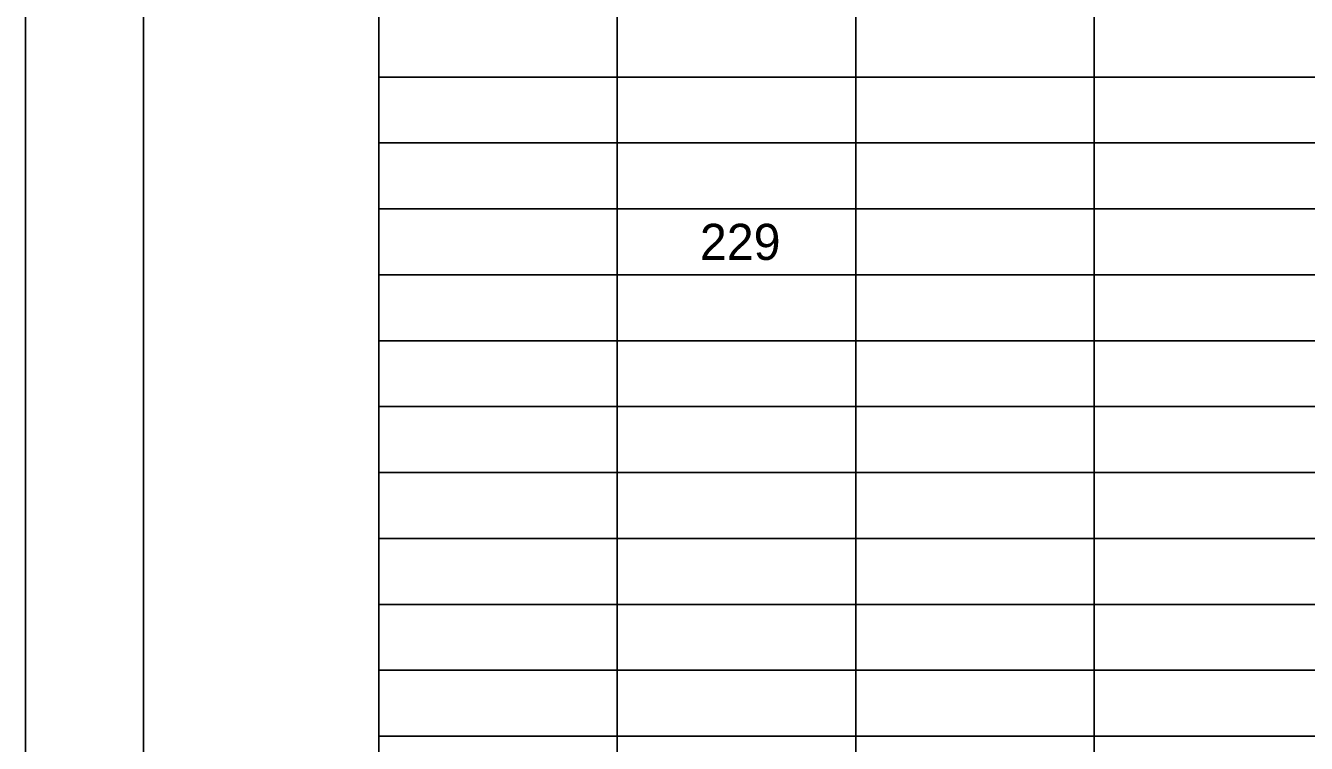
# Model space of a CAD drawing. Extents: x 0 to 34, y 0 to 22.
# Drawn here: x 0 to 5.44, y 15.87 to 18.92 of the extents above; entities that cross this region are included whole.
import ezdxf

# ---------------------------------------------------------------- set-up
doc = ezdxf.new("R2010")
doc.units = 0
for name, color, linetype in [('SH_Border', 7, 'Continuous'), ('SH_Cut_Line', 7, 'Continuous'), ('SH_Text', 7, 'Continuous')]:
    doc.layers.add(name, color=color, linetype=linetype)

msp = doc.modelspace()

# ---------------------------------------------------------------- linework, layer by layer
at = {"layer": 'SH_Border'}
for points in [[(0.5, 21.5), (1.5, 21.5), (1.5, 0.5), (0.5, 0.5)], [(1.5, 21.5), (33.5, 21.5), (33.5, 0.5), (1.5, 0.5)]]:
    msp.add_lwpolyline(points, close=True, dxfattribs=at)
at = {"layer": 'SH_Cut_Line'}
msp.add_lwpolyline([(0, 0), (34, 0), (34, 22), (0, 22)], close=True, dxfattribs=at)
at = {"layer": 'SH_Text'}
for p, q in [((1.5, 20.1), (1.5, 18.7)), ((2.5119, 20.1), (2.5119, 18.7)), ((3.5238, 20.1), (3.5238, 18.7)), ((4.5357, 20.1), (4.5357, 18.7)), ((1.5, 18.7), (6.5595, 18.7)), ((1.5, 18.7), (1.5, 18.14)), ((2.5119, 18.7), (2.5119, 18.14)), ((3.5238, 18.7), (3.5238, 18.14)), ((4.5357, 18.7), (4.5357, 18.14)), ((1.5, 18.42), (6.5595, 18.42)), ((1.5, 18.14), (6.5595, 18.14)), ((1.5, 18.14), (1.5, 17.86)), ((2.5119, 18.14), (2.5119, 17.86)), ((3.5238, 18.14), (3.5238, 17.86)), ((4.5357, 18.14), (4.5357, 17.86)), ((1.5, 17.86), (6.5595, 17.86)), ((1.5, 17.86), (1.5, 17.58)), ((2.5119, 17.86), (2.5119, 17.58)), ((3.5238, 17.86), (3.5238, 17.58)), ((4.5357, 17.86), (4.5357, 17.58)), ((1.5, 17.58), (6.5595, 17.58)), ((1.5, 17.58), (1.5, 17.3)), ((2.5119, 17.58), (2.5119, 17.3)), ((3.5238, 17.58), (3.5238, 17.3)), ((4.5357, 17.58), (4.5357, 17.3)), ((1.5, 17.3), (6.5595, 17.3)), ((1.5, 17.3), (1.5, 17.02)), ((2.5119, 17.3), (2.5119, 17.02)), ((3.5238, 17.3), (3.5238, 17.02)), ((4.5357, 17.3), (4.5357, 17.02)), ((1.5, 17.02), (6.5595, 17.02)), ((1.5, 17.02), (1.5, 16.74)), ((2.5119, 17.02), (2.5119, 16.74)), ((3.5238, 17.02), (3.5238, 16.74)), ((4.5357, 17.02), (4.5357, 16.74)), ((1.5, 16.74), (6.5595, 16.74)), ((1.5, 16.74), (1.5, 16.18)), ((2.5119, 16.74), (2.5119, 16.18)), ((3.5238, 16.74), (3.5238, 16.18)), ((4.5357, 16.74), (4.5357, 16.18)), ((1.5, 16.46), (6.5595, 16.46)), ((1.5, 16.18), (6.5595, 16.18)), ((1.5, 16.18), (1.5, 15.9)), ((2.5119, 16.18), (2.5119, 15.9)), ((3.5238, 16.18), (3.5238, 15.9)), ((4.5357, 16.18), (4.5357, 15.9)), ((1.5, 15.9), (6.5595, 15.9)), ((1.5, 15.9), (1.5, 15.62)), ((2.5119, 15.9), (2.5119, 15.62)), ((3.5238, 15.9), (3.5238, 15.62)), ((4.5357, 15.9), (4.5357, 15.62))]:
    msp.add_line(p, q, dxfattribs=at)

# ---------------------------------------------------------------- texts
msp.add_text('229', height=0.15333, dxfattribs=at).set_placement((2.8625, 17.9233))

doc.saveas('drawing.dxf')
